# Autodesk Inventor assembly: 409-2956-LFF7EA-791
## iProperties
Created: 2010-09
Part Number: 409-2956-LFF7EA-791
Document SubType Name: Weldment
Designer: S. Boerckel
Weld Material: Welded Aluminum-6061
Mass: 5214.49 g
Surface Area: 2191.08 cm^2
Volume: 664.267 cm^3
Density: 7.85 g/cm^3
Description: DISCHARGE PIPE STAND
Material: WELDMENT
SMR: =<MATERIAL>
Author: S. Boerckel
Revision Number: A
